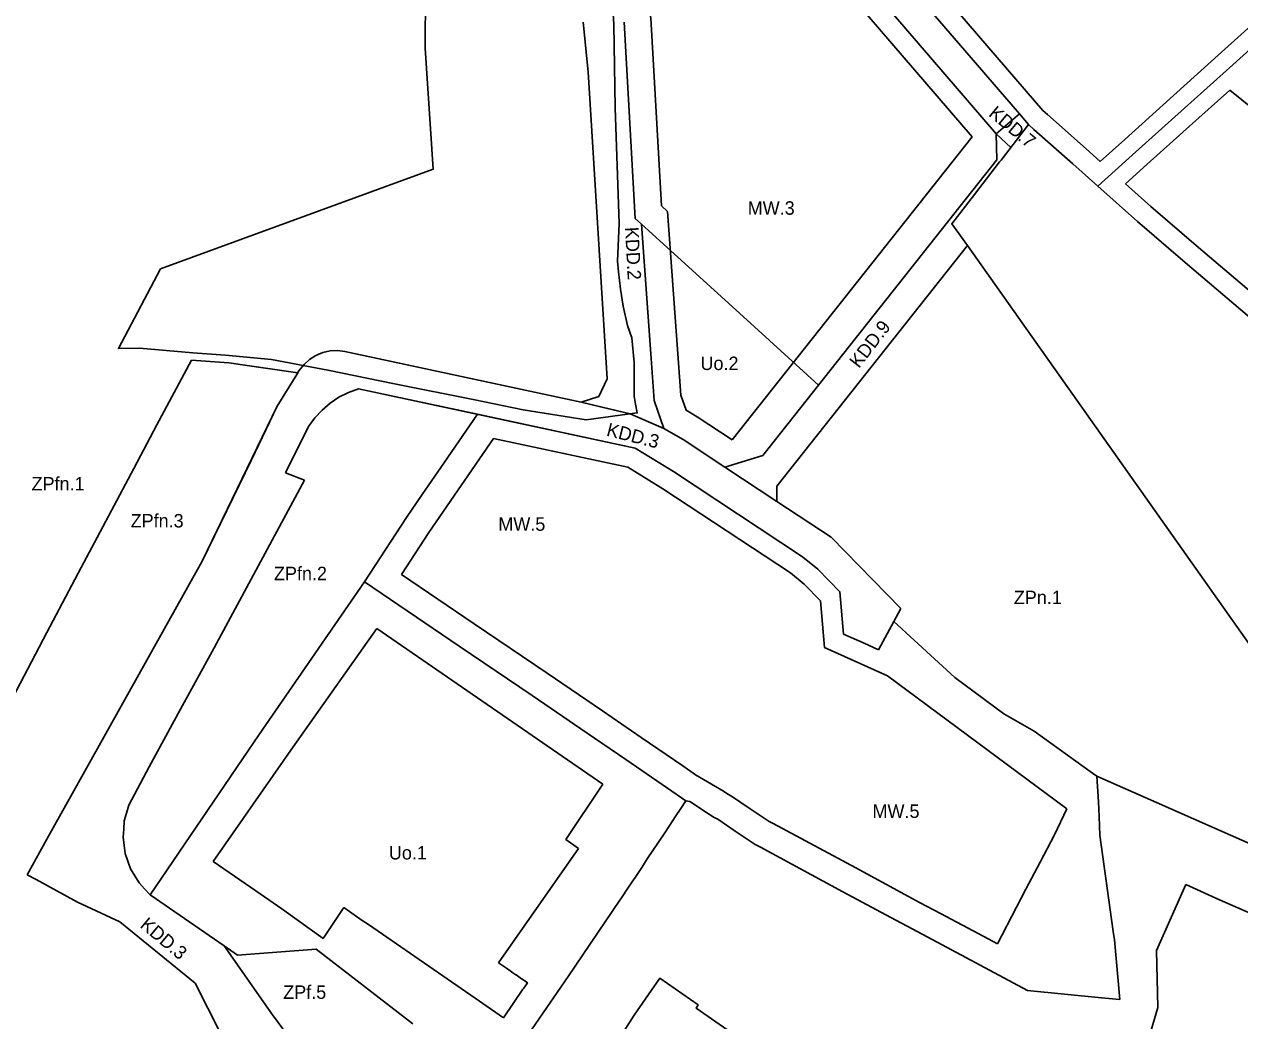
# Model space of a CAD drawing. Extents: x 7432050 to 7433361, y 5551438 to 5552391.
# Drawn here: x 7432631.9 to 7432993.3, y 5551658.9 to 5551955.2 of the extents above; entities that cross this region are included whole.
import ezdxf

# ---------------------------------------------------------------- set-up
doc = ezdxf.new("R2010")
doc.units = 0
for name, color, linetype in [('linie rozgraniczające', 7, 'Continuous'), ('MPZP_Niebyla_Na_Wzgorzach', 7, 'Continuous'), ('nieprzekraczalne linie zabudowy', 7, 'Continuous'), ('oznaczenia przeznaczen', 7, 'Continuous')]:
    doc.layers.add(name, color=color, linetype=linetype)

msp = doc.modelspace()

# ---------------------------------------------------------------- linework, layer by layer
at = {"layer": 'linie rozgraniczające'}
for p, q in [((7432927.77, 5551928.55), (7432866.31, 5551999.9)), ((7432866.31, 5551999.9), (7432927.77, 5551928.55)), ((7432890.38, 5551958.13), (7432920.91, 5551922.63)), ((7432920.91, 5551922.63), (7432890.38, 5551958.13)), ((7432798.13, 5551955.82), (7432799.6, 5551941.11)), ((7432799.6, 5551941.11), (7432798.13, 5551955.82)), ((7432813.58, 5551897.47), (7432810.24, 5551955.85)), ((7432810.24, 5551955.85), (7432813.58, 5551897.47)), ((7433001.88, 5551952.8), (7432991.21, 5551943.19)), ((7432991.21, 5551943.19), (7433001.88, 5551952.8)), ((7432799.6, 5551941.11), (7432803.45, 5551878.53)), ((7432803.45, 5551878.53), (7432799.6, 5551941.11)), ((7432991.21, 5551943.19), (7432976.89, 5551930.3)), ((7432976.89, 5551930.3), (7432991.21, 5551943.19)), ((7432976.89, 5551930.3), (7432962.43, 5551917.28)), ((7432962.43, 5551917.28), (7432976.89, 5551930.3)), ((7432920.91, 5551922.63), (7432927.77, 5551928.55)), ((7432920.91, 5551922.63), (7432927.77, 5551928.55)), ((7432927.77, 5551928.55), (7432920.91, 5551922.63)), ((7432921.07, 5551914.92), (7432920.91, 5551922.63)), ((7432920.91, 5551922.63), (7432925.22, 5551918.56)), ((7432868.05, 5551847.94), (7432921.07, 5551914.92)), ((7432962.43, 5551917.28), (7432951.09, 5551907.07)), ((7432951.09, 5551907.07), (7432962.43, 5551917.28)), ((7432943.68, 5551913.66), (7432951.09, 5551907.07)), ((7432951.09, 5551907.07), (7432943.68, 5551913.66)), ((7432951.09, 5551907.07), (7432962.92, 5551896.55)), ((7432962.92, 5551896.55), (7432951.09, 5551907.07)), ((7432815.41, 5551895.81), (7432813.58, 5551897.47)), ((7432813.58, 5551897.47), (7432815.41, 5551895.81)), ((7432962.92, 5551896.55), (7432977.09, 5551884.32)), ((7432977.09, 5551884.32), (7432962.92, 5551896.55)), ((7432818.21, 5551857.2), (7432815.41, 5551895.81)), ((7432815.41, 5551895.81), (7432837.05, 5551876.12)), ((7432837.05, 5551876.12), (7432815.41, 5551895.81)), ((7432815.41, 5551895.81), (7432818.21, 5551857.2)), ((7432977.09, 5551884.32), (7433000.73, 5551864.23)), ((7433000.73, 5551864.23), (7432977.09, 5551884.32)), ((7432803.45, 5551878.53), (7432805.26, 5551849.77)), ((7432805.26, 5551849.77), (7432803.45, 5551878.53)), ((7432837.05, 5551876.12), (7432845.66, 5551868.3)), ((7432845.66, 5551868.3), (7432837.05, 5551876.12)), ((7432845.66, 5551868.3), (7432868.05, 5551847.94)), ((7432868.05, 5551847.94), (7432845.66, 5551868.3)), ((7432716.75, 5551855.55), (7432718.63, 5551856.73)), ((7432718.63, 5551856.73), (7432720.68, 5551857.58)), ((7432720.68, 5551857.58), (7432722.84, 5551858.06)), ((7432722.84, 5551858.06), (7432725.05, 5551858.17)), ((7432725.05, 5551858.17), (7432727.25, 5551857.9)), ((7432727.25, 5551857.9), (7432733.24, 5551856.62)), ((7432733.24, 5551856.62), (7432727.25, 5551857.9)), ((7432819.22, 5551843.32), (7432818.21, 5551857.2)), ((7432818.21, 5551857.2), (7432819.22, 5551843.32)), ((7432671.38, 5551836.06), (7432681.69, 5551855.34)), ((7432681.69, 5551855.34), (7432671.38, 5551836.06)), ((7432681.69, 5551855.34), (7432692.71, 5551854.5)), ((7432692.71, 5551854.5), (7432681.69, 5551855.34)), ((7432692.71, 5551854.5), (7432713.26, 5551851.58)), ((7432713.49, 5551852.02), (7432715.1, 5551854.07)), ((7432715.1, 5551854.07), (7432713.49, 5551852.02)), ((7432715.1, 5551854.07), (7432716.75, 5551855.55)), ((7432733.24, 5551856.62), (7432797.48, 5551842.85)), ((7432797.48, 5551842.85), (7432733.24, 5551856.62)), ((7432707.15, 5551841.63), (7432712.96, 5551851.09)), ((7432712.96, 5551851.09), (7432707.15, 5551841.63)), ((7432712.96, 5551851.09), (7432713.26, 5551851.58)), ((7432713.26, 5551851.58), (7432712.96, 5551851.09)), ((7432713.26, 5551851.58), (7432713.49, 5551852.02)), ((7432713.49, 5551852.02), (7432713.26, 5551851.58)), ((7432813.59, 5551829.17), (7432731.27, 5551846.81)), ((7432731.27, 5551846.81), (7432766.64, 5551839.23)), ((7432851.49, 5551827.01), (7432868.05, 5551847.94)), ((7432797.48, 5551842.85), (7432803.26, 5551841.46)), ((7432803.26, 5551841.46), (7432797.48, 5551842.85)), ((7432822.11, 5551834.97), (7432819.22, 5551843.32)), ((7432819.22, 5551843.32), (7432822.11, 5551834.97)), ((7432707.15, 5551841.63), (7432684.83, 5551795.54)), ((7432699.44, 5551825.71), (7432707.15, 5551841.63)), ((7432766.64, 5551839.23), (7432756.65, 5551824.68)), ((7432813.59, 5551829.17), (7432766.64, 5551839.23)), ((7432766.64, 5551839.23), (7432813.59, 5551829.17)), ((7432803.26, 5551841.46), (7432812.09, 5551839.34)), ((7432812.09, 5551839.34), (7432822.11, 5551834.97)), ((7432664.48, 5551823.09), (7432671.38, 5551836.06)), ((7432671.38, 5551836.06), (7432664.48, 5551823.09)), ((7432709.62, 5551821.83), (7432716.47, 5551835.61)), ((7432822.11, 5551834.97), (7432827.79, 5551831.71)), ((7432827.79, 5551831.71), (7432822.11, 5551834.97)), ((7432827.79, 5551831.71), (7432840.16, 5551823.56)), ((7432840.16, 5551823.56), (7432827.79, 5551831.71)), ((7432824.99, 5551822.18), (7432813.59, 5551829.17)), ((7432813.59, 5551829.17), (7432824.99, 5551822.18)), ((7432684.83, 5551795.54), (7432699.44, 5551825.71)), ((7432756.65, 5551824.68), (7432750.26, 5551815.38)), ((7432840.16, 5551823.56), (7432851.49, 5551827.01)), ((7432652.79, 5551801.11), (7432664.48, 5551823.09)), ((7432664.48, 5551823.09), (7432652.79, 5551801.11)), ((7432715.21, 5551819.69), (7432709.62, 5551821.83)), ((7432863.33, 5551796.9), (7432824.99, 5551822.18)), ((7432824.99, 5551822.18), (7432863.33, 5551796.9)), ((7432688.34, 5551769.78), (7432715.21, 5551819.69)), ((7432750.26, 5551815.38), (7432745.58, 5551808.57)), ((7432745.58, 5551808.57), (7432733.05, 5551789.4)), ((7432892.57, 5551781.51), (7432871.87, 5551802.65)), ((7432648.81, 5551793.72), (7432652.79, 5551801.11)), ((7432652.79, 5551801.11), (7432648.81, 5551793.72)), ((7432665.48, 5551761.02), (7432684.83, 5551795.54)), ((7432684.83, 5551795.54), (7432665.48, 5551761.02)), ((7432867.85, 5551793.18), (7432863.33, 5551796.9)), ((7432863.33, 5551796.9), (7432867.85, 5551793.18)), ((7432638.67, 5551774.34), (7432648.81, 5551793.72)), ((7432648.81, 5551793.72), (7432638.67, 5551774.34)), ((7432733.05, 5551789.4), (7432701.77, 5551743.98)), ((7432761.23, 5551770.3), (7432733.05, 5551789.4)), ((7432733.05, 5551789.4), (7432761.23, 5551770.3)), ((7432890.47, 5551777.63), (7432892.57, 5551781.51)), ((7432890.47, 5551777.63), (7432885.92, 5551769.21)), ((7432885.92, 5551769.21), (7432890.47, 5551777.63)), ((7432908.62, 5551760.93), (7432890.47, 5551777.63)), ((7432627.31, 5551752.71), (7432638.67, 5551774.34)), ((7432638.67, 5551774.34), (7432627.31, 5551752.71)), ((7432881.6, 5551771.15), (7432875.52, 5551773.88)), ((7432875.52, 5551773.88), (7432881.6, 5551771.15)), ((7432782.89, 5551755.65), (7432761.23, 5551770.3)), ((7432761.23, 5551770.3), (7432782.89, 5551755.65)), ((7432885.92, 5551769.21), (7432881.6, 5551771.15)), ((7432881.6, 5551771.15), (7432885.92, 5551769.21)), ((7432678.38, 5551751.54), (7432688.34, 5551769.78)), ((7432638.68, 5551712.89), (7432665.48, 5551761.02)), ((7432665.48, 5551761.02), (7432638.68, 5551712.89)), ((7432923.16, 5551750.17), (7432908.62, 5551760.93)), ((7432799.27, 5551744.44), (7432782.89, 5551755.65)), ((7432782.89, 5551755.65), (7432799.27, 5551744.44)), ((7432669.05, 5551734.43), (7432678.38, 5551751.54)), ((7432932.17, 5551745.06), (7432923.16, 5551750.17)), ((7432949.51, 5551732.51), (7432932.17, 5551745.06)), ((7432701.77, 5551743.98), (7432669.37, 5551696.31)), ((7432810.78, 5551736.57), (7432799.27, 5551744.44)), ((7432799.27, 5551744.44), (7432810.78, 5551736.57)), ((7432823.13, 5551728.11), (7432810.78, 5551736.57)), ((7432810.78, 5551736.57), (7432823.13, 5551728.11)), ((7432950.78, 5551731.59), (7432949.51, 5551732.51)), ((7432951.3, 5551724.03), (7432950.78, 5551731.59)), ((7433026.86, 5551698), (7432950.78, 5551731.59)), ((7432950.78, 5551731.59), (7432951.3, 5551724.03)), ((7432828.6, 5551724.26), (7432823.13, 5551728.11)), ((7432823.13, 5551728.11), (7432828.6, 5551724.26)), ((7432827.14, 5551722.05), (7432828.6, 5551724.26)), ((7432828.6, 5551724.26), (7432827.14, 5551722.05)), ((7432828.6, 5551724.26), (7432829.8, 5551724.14)), ((7432829.8, 5551724.14), (7432828.6, 5551724.26)), ((7432829.8, 5551724.14), (7432835.4, 5551720.47)), ((7432835.4, 5551720.47), (7432829.8, 5551724.14)), ((7432951.48, 5551719.61), (7432951.3, 5551724.03)), ((7432951.3, 5551724.03), (7432951.48, 5551719.61)), ((7432823.84, 5551717.09), (7432825.48, 5551719.55)), ((7432825.48, 5551719.55), (7432823.84, 5551717.09)), ((7432825.48, 5551719.55), (7432827.14, 5551722.05)), ((7432827.14, 5551722.05), (7432825.48, 5551719.55)), ((7432835.4, 5551720.47), (7432837.07, 5551719.37)), ((7432837.07, 5551719.37), (7432835.4, 5551720.47)), ((7432837.07, 5551719.37), (7432838.11, 5551718.83)), ((7432838.11, 5551718.83), (7432837.07, 5551719.37)), ((7432951.71, 5551714.05), (7432951.48, 5551719.61)), ((7432951.48, 5551719.61), (7432951.71, 5551714.05)), ((7432822.13, 5551714.51), (7432823.84, 5551717.09)), ((7432823.84, 5551717.09), (7432822.13, 5551714.51)), ((7432838.11, 5551718.83), (7432843.25, 5551715.29)), ((7432843.25, 5551715.29), (7432838.11, 5551718.83)), ((7432632.78, 5551702.29), (7432638.68, 5551712.89)), ((7432638.68, 5551712.89), (7432632.78, 5551702.29)), ((7432820.45, 5551711.97), (7432822.13, 5551714.51)), ((7432822.13, 5551714.51), (7432820.45, 5551711.97)), ((7432843.25, 5551715.29), (7432849.26, 5551711.33)), ((7432849.26, 5551711.33), (7432843.25, 5551715.29)), ((7432955.7, 5551685.44), (7432951.71, 5551714.05)), ((7432951.71, 5551714.05), (7432955.7, 5551685.44)), ((7432817.15, 5551707.02), (7432818.81, 5551709.52)), ((7432818.81, 5551709.52), (7432817.15, 5551707.02)), ((7432818.81, 5551709.52), (7432820.45, 5551711.97)), ((7432820.45, 5551711.97), (7432818.81, 5551709.52)), ((7432849.26, 5551711.33), (7432850.79, 5551710.51)), ((7432850.79, 5551710.51), (7432849.26, 5551711.33)), ((7432850.79, 5551710.51), (7432875.33, 5551697.29)), ((7432875.33, 5551697.29), (7432850.79, 5551710.51)), ((7432815.49, 5551704.52), (7432817.15, 5551707.02)), ((7432817.15, 5551707.02), (7432815.49, 5551704.52)), ((7432666.04, 5551699.87), (7432664.78, 5551701.96)), ((7432811.56, 5551698.61), (7432813.72, 5551701.85)), ((7432813.72, 5551701.85), (7432811.56, 5551698.61)), ((7432813.72, 5551701.85), (7432815.49, 5551704.52)), ((7432815.49, 5551704.52), (7432813.72, 5551701.85)), ((7432667.7, 5551698.09), (7432666.04, 5551699.87)), ((7432669.37, 5551696.31), (7432667.7, 5551698.09)), ((7432809.27, 5551695.15), (7432811.56, 5551698.61)), ((7432811.56, 5551698.61), (7432809.27, 5551695.15)), ((7432669.37, 5551696.31), (7432691.39, 5551681.14)), ((7432691.39, 5551681.14), (7432669.37, 5551696.31)), ((7432793.64, 5551672.05), (7432809, 5551694.76)), ((7432809, 5551694.76), (7432793.64, 5551672.05)), ((7432809, 5551694.76), (7432809.27, 5551695.15)), ((7432809.27, 5551695.15), (7432809, 5551694.76)), ((7432875.33, 5551697.29), (7432891, 5551688.83)), ((7432891, 5551688.83), (7432875.33, 5551697.29)), ((7432660.35, 5551688.32), (7432650.57, 5551692.86)), ((7432650.57, 5551692.86), (7432660.35, 5551688.32)), ((7432682.77, 5551670.1), (7432660.35, 5551688.32)), ((7432660.35, 5551688.32), (7432682.77, 5551670.1)), ((7432891, 5551688.83), (7432894.38, 5551687.04)), ((7432894.38, 5551687.04), (7432891, 5551688.83)), ((7432894.38, 5551687.04), (7432900.54, 5551683.77)), ((7432900.54, 5551683.77), (7432894.38, 5551687.04)), ((7432900.54, 5551683.77), (7432911.9, 5551677.68)), ((7432911.9, 5551677.68), (7432900.54, 5551683.77)), ((7432956.04, 5551682.97), (7432955.7, 5551685.44)), ((7432955.7, 5551685.44), (7432956.04, 5551682.97)), ((7432691.39, 5551681.14), (7432695.37, 5551678.39)), ((7432705.68, 5551660.68), (7432691.39, 5551681.14)), ((7432695.37, 5551678.39), (7432718.68, 5551680.18)), ((7432718.68, 5551680.18), (7432747.44, 5551658.04)), ((7432957.63, 5551665.23), (7432956.04, 5551682.97)), ((7432956.04, 5551682.97), (7432957.63, 5551665.23)), ((7432911.9, 5551677.68), (7432930.17, 5551667.89)), ((7432930.17, 5551667.89), (7432911.9, 5551677.68)), ((7432690.3, 5551655.18), (7432682.77, 5551670.1)), ((7432682.77, 5551670.1), (7432690.3, 5551655.18)), ((7432781.82, 5551654.95), (7432793.64, 5551672.05)), ((7432793.64, 5551672.05), (7432781.82, 5551654.95)), ((7432930.17, 5551667.89), (7432952.22, 5551665.76)), ((7432952.22, 5551665.76), (7432930.17, 5551667.89)), ((7432952.22, 5551665.76), (7432957.63, 5551665.23)), ((7432957.63, 5551665.23), (7432952.22, 5551665.76)), ((7432710.81, 5551653.82), (7432705.68, 5551660.68))]:
    msp.add_line(p, q, dxfattribs=at)
for points in [[(7432927.77, 5551928.55), (7432930.5, 5551925.38), (7432932.1, 5551923.94), (7432943.68, 5551913.66)], [(7432943.68, 5551913.66), (7432932.1, 5551923.94), (7432930.5, 5551925.38), (7432927.77, 5551928.55)], [(7432855.65, 5551813.34), (7432855.7, 5551817.84), (7432912.36, 5551889.43)], [(7432727.25, 5551857.9), (7432725.05, 5551858.17), (7432722.84, 5551858.06), (7432720.68, 5551857.58), (7432718.63, 5551856.73), (7432716.75, 5551855.55), (7432715.1, 5551854.07)], [(7432727.25, 5551857.9), (7432725.05, 5551858.17), (7432722.84, 5551858.06), (7432720.68, 5551857.58), (7432718.63, 5551856.73), (7432716.75, 5551855.55), (7432715.1, 5551854.07)], [(7432797.48, 5551842.85), (7432727.25, 5551857.9)], [(7432713.26, 5551851.58), (7432702.99, 5551853.04), (7432692.71, 5551854.5)], [(7432805.26, 5551849.77), (7432802.7, 5551844.55), (7432797.48, 5551842.85)], [(7432797.48, 5551842.85), (7432802.7, 5551844.55), (7432805.26, 5551849.77)], [(7432716.47, 5551835.61), (7432718.32, 5551838.17), (7432720.46, 5551840.49), (7432722.86, 5551842.54), (7432725.49, 5551844.29), (7432728.3, 5551845.72), (7432731.27, 5551846.81)], [(7432797.48, 5551842.85), (7432812.09, 5551839.34), (7432822.11, 5551834.97)], [(7432822.11, 5551834.97), (7432812.09, 5551839.34), (7432803.26, 5551841.46)], [(7432871.87, 5551802.65), (7432855.65, 5551813.34), (7432840.16, 5551823.56)], [(7432875.52, 5551773.88), (7432874.44, 5551786.45), (7432867.85, 5551793.18)], [(7432867.85, 5551793.18), (7432874.44, 5551786.45), (7432875.52, 5551773.88)], [(7432664.78, 5551701.96), (7432663.52, 5551704.04), (7432662.71, 5551706.34), (7432661.91, 5551708.65), (7432661.6, 5551711.06), (7432661.29, 5551713.48), (7432661.48, 5551715.91), (7432661.67, 5551718.34), (7432662.37, 5551720.68), (7432663.06, 5551723.02), (7432669.05, 5551734.43)], [(7432650.57, 5551692.86), (7432647.74, 5551694.17), (7432641.58, 5551697.51), (7432635.42, 5551700.86), (7432632.78, 5551702.29)], [(7432632.78, 5551702.29), (7432635.42, 5551700.86), (7432641.58, 5551697.51)], [(7432641.58, 5551697.51), (7432647.74, 5551694.17), (7432650.57, 5551692.86)]]:
    msp.add_lwpolyline(points, dxfattribs=at)
at = {"layer": 'MPZP_Niebyla_Na_Wzgorzach'}
for points in [[(7432806.67, 5551963.31), (7432807.2, 5551955.16), (7432807.64, 5551930.4), (7432808.79, 5551895.98), (7432808.34, 5551884.72), (7432808.63, 5551881.56), (7432809.17, 5551876.44), (7432809.98, 5551871.34), (7432811.26, 5551865.63), (7432812.59, 5551862.01), (7432813.25, 5551854.67), (7432813.26, 5551849.63), (7432813.21, 5551844.63), (7432813.66, 5551842.23), (7432814.18, 5551839.63), (7432798.99, 5551837.55), (7432780.23, 5551840.58), (7432765.86, 5551843.54), (7432742.02, 5551848.32), (7432722.19, 5551852.36), (7432705.41, 5551855.55), (7432691.78, 5551856.79), (7432682.08, 5551857.54), (7432666.16, 5551858.93), (7432659.93, 5551858.79), (7432672.47, 5551882.46), (7432753.52, 5551912.12), (7432751.07, 5551948.06), (7432751.54, 5552014)], [(7433049.29, 5551695.66), (7432912.36, 5551889.43), (7432907.67, 5551895.86), (7432914.43, 5551904.6), (7432921.91, 5551914.27), (7432922.34, 5551914.83), (7432930.5, 5551925.38), (7432932.1, 5551923.94), (7432942.1, 5551915.06), (7432943.68, 5551913.66), (7432951.09, 5551907.07), (7432962.92, 5551896.55), (7432977.09, 5551884.32), (7433000.73, 5551864.23)]]:
    msp.add_lwpolyline(points, dxfattribs=at)
at = {"layer": 'nieprzekraczalne linie zabudowy'}
for p, q in [((7433013.3, 5551917.06), (7432990.3, 5551935.65)), ((7432821.38, 5551901.2), (7432823.16, 5551899.58)), ((7432811.36, 5551823.51), (7432771.43, 5551832.07)), ((7432803.94, 5551729.28), (7432736.77, 5551775.56)), ((7432941.93, 5551721.96), (7432888.55, 5551761.45)), ((7432772.94, 5551676.1), (7432796.73, 5551710.13)), ((7432977.31, 5551699.38), (7432968.59, 5551679.75)), ((7432720.81, 5551683.34), (7432726.93, 5551692.54)), ((7432726.93, 5551692.54), (7432732.42, 5551688.75)), ((7432775.25, 5551674.5), (7432772.94, 5551676.1)), ((7432777.15, 5551673.19), (7432776.4, 5551673.71)), ((7432779.81, 5551671.36), (7432779.76, 5551671.4)), ((7432761.81, 5551668.47), (7432761.81, 5551668.47)), ((7432780.2, 5551668.26), (7432780.42, 5551668.58))]:
    msp.add_line(p, q, dxfattribs=at)
for points in [[(7432798.21, 5552073.73), (7432803.27, 5552072.22), (7432807.87, 5552069.73), (7432809.54, 5552068.2), (7432811.01, 5552066.77), (7432812.47, 5552065.16), (7432814.25, 5552062.92), (7432815.54, 5552061.03), (7432816.97, 5552058.56), (7432818.27, 5552055.82), (7432819.07, 5552053.93), (7432822.03, 5552048.62), (7432837.79, 5552034.17), (7432861.09, 5552012.8), (7432867.67, 5552006.79), (7432870.62, 5552004.09), (7432932.32, 5551932.46), (7432934.8, 5551929.59), (7432936.1, 5551928.41), (7432947.67, 5551918.15), (7432951.82, 5551914.45)], [(7432803.82, 5552036.63), (7432806.71, 5552021.49), (7432811.03, 5551997.47), (7432813.68, 5551986.49), (7432815.74, 5551967.18), (7432818.18, 5551957.02), (7432821.38, 5551901.2)], [(7432913.74, 5551921.77), (7432855.52, 5551989.44), (7432847.25, 5551997.08), (7432806.3, 5552034.63), (7432804.35, 5552036.91)], [(7432951.82, 5551914.45), (7432959.08, 5551920.99), (7432973.55, 5551934.02), (7432987.86, 5551946.91), (7433012.27, 5551968.89)], [(7432990.3, 5551935.65), (7432980.24, 5551926.59), (7432965.77, 5551913.56), (7432959.34, 5551907.77)], [(7432842.41, 5551831.65), (7432913.74, 5551921.77)], [(7432959.34, 5551907.77), (7432966.87, 5551901.06), (7432980.99, 5551888.87), (7433004.5, 5551868.9), (7433019.43, 5551857.39), (7433021.81, 5551855.43)], [(7432823.16, 5551899.58), (7432827.12, 5551844.94), (7432828.69, 5551840.42), (7432831.99, 5551838.52), (7432842.41, 5551831.65)], [(7432771.43, 5551832.07), (7432752.23, 5551804.12), (7432744.05, 5551791.61)], [(7432888.55, 5551761.45), (7432869.84, 5551769.85), (7432868.65, 5551783.79), (7432863.79, 5551788.75), (7432859.76, 5551792.07), (7432821.77, 5551817.12), (7432811.33, 5551823.51)], [(7432744.05, 5551791.61), (7432765.71, 5551776.92), (7432787.38, 5551762.26), (7432803.79, 5551751.05), (7432815.3, 5551743.17), (7432827.7, 5551734.68), (7432831.5, 5551732), (7432839.8, 5551727.15), (7432841.12, 5551726.28), (7432842.23, 5551725.71), (7432847.72, 5551721.93), (7432853.37, 5551718.2), (7432854.58, 5551717.55), (7432879.13, 5551704.33), (7432894.77, 5551695.88), (7432898.13, 5551694.1), (7432904.3, 5551690.83), (7432915.68, 5551684.73), (7432921.27, 5551681.74)], [(7432736.77, 5551775.56), (7432714.1, 5551743.41), (7432711.21, 5551739.33), (7432708.92, 5551736.06), (7432688.09, 5551706.3)], [(7432796.73, 5551710.13), (7432792.96, 5551712.82), (7432803.94, 5551729.28)], [(7432921.27, 5551681.74), (7432922.67, 5551684.42), (7432925.57, 5551689.98), (7432929.74, 5551698.03), (7432933.91, 5551706.07), (7432938.24, 5551714.23), (7432941.93, 5551721.96)], [(7432688.09, 5551706.3), (7432696.06, 5551700.8), (7432700.79, 5551697.54), (7432708.52, 5551692.22), (7432720.81, 5551683.34)], [(7433050.13, 5551667.12), (7433040.22, 5551671.58), (7433029.07, 5551676.49), (7433026.25, 5551677.77), (7433015.03, 5551682.69), (7433012.26, 5551683.94), (7433001.05, 5551688.83), (7432998.21, 5551690.1), (7432987.31, 5551694.87), (7432977.31, 5551699.38)], [(7432732.42, 5551688.75), (7432734.24, 5551687.5), (7432761.78, 5551668.49)], [(7432968.59, 5551679.75), (7432968.91, 5551662.87), (7432965.67, 5551651.72), (7432892.55, 5551639.17)], [(7432776.4, 5551673.71), (7432775.25, 5551674.5), (7432775.25, 5551674.5)], [(7432778.06, 5551672.57), (7432777.15, 5551673.19), (7432777.15, 5551673.19)], [(7432779.76, 5551671.4), (7432778.13, 5551672.52), (7432778.06, 5551672.57)], [(7432780.8, 5551670.68), (7432780.8, 5551670.68), (7432779.81, 5551671.36)], [(7432780.42, 5551668.58), (7432781.52, 5551670.18), (7432780.8, 5551670.68)], [(7432892.55, 5551639.17), (7432852.08, 5551647.07), (7432841.41, 5551654.32), (7432842.1, 5551655.45), (7432831.65, 5551662.69), (7432832.27, 5551663.62), (7432820.84, 5551671.53), (7432813.24, 5551660.54), (7432801.85, 5551642.62), (7432792.04, 5551633.94), (7432809.37, 5551614.23), (7432810.26, 5551614.85), (7432819.05, 5551605.16), (7432819.83, 5551605.73), (7432828.62, 5551596.32), (7432844.86, 5551583.49), (7432876.55, 5551576.98), (7432884.62, 5551617.91), (7432894.81, 5551615.85), (7432968.76, 5551630.02)], [(7432761.78, 5551668.49), (7432761.81, 5551668.47), (7432761.81, 5551668.47)], [(7432761.81, 5551668.47), (7432765.94, 5551665.62), (7432774.37, 5551659.81), (7432780.2, 5551668.26)]]:
    msp.add_lwpolyline(points, dxfattribs=at)

# ---------------------------------------------------------------- texts
at = {"layer": 'oznaczenia przeznaczen'}
for s, rotation, p in [('KDD.7', 320.4551, (7432918.38, 5551928.17)), ('KDD.2', 273.0587, (7432810.52, 5551894.84)), ('KDD.9', 52.1274, (7432880.06, 5551852.71)), ('KDD.3', 345.8878, (7432804.79, 5551832.9)), ('KDD.3', 320.0809, (7432666.09, 5551686.9))]:
    msp.add_text(s, height=4, rotation=rotation, dxfattribs=at).set_placement(p)
for s, p in [('MW.3', (7432847.01, 5551898.57)), ('Uo.2', (7432832.97, 5551852.39)), ('ZPfn.1', (7432634.1, 5551816.59)), ('ZPfn.3', (7432663.55, 5551805.58)), ('MW.5', (7432772.87, 5551804.59)), ('ZPfn.2', (7432706.16, 5551789.91)), ('ZPn.1', (7432926.13, 5551782.78)), ('MW.5', (7432884.11, 5551719.21)), ('Uo.1', (7432740.33, 5551706.86)), ('ZPf.5', (7432708.92, 5551665.42))]:
    msp.add_text(s, height=4, dxfattribs=at).set_placement(p)

doc.saveas('drawing.dxf')
